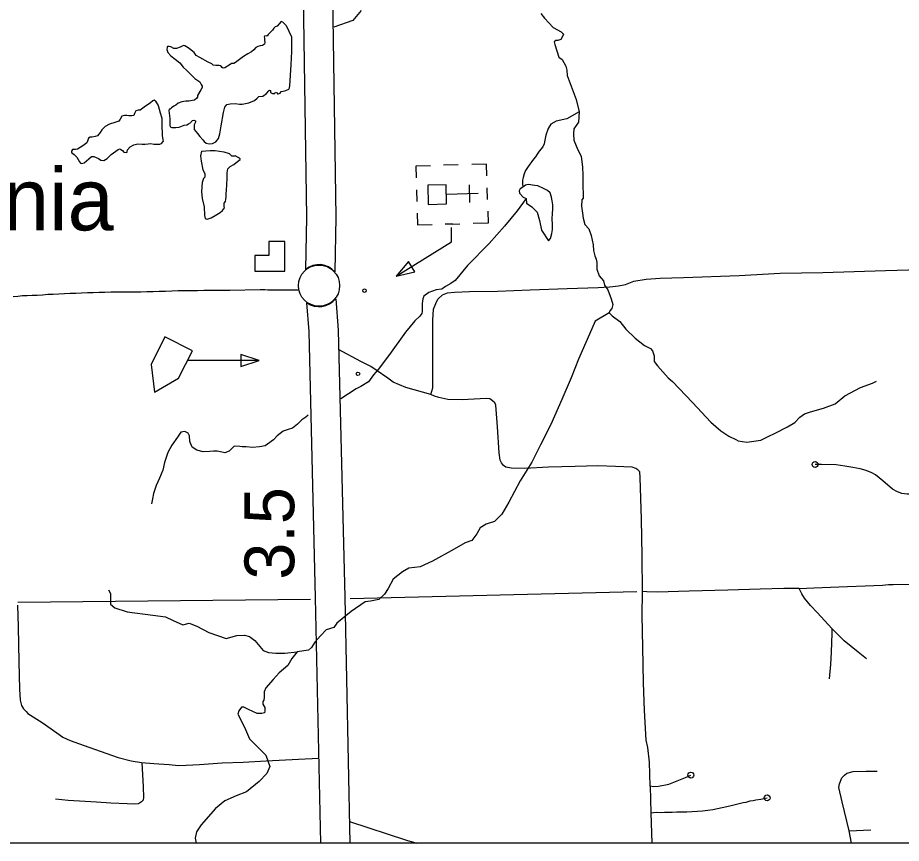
# Model space of a CAD drawing. Extents: x 1367863 to 1368197, y 380048 to 380261.
# Drawn here: x 1368043.62 to 1368072.73, y 380096.87 to 380124.07 of the extents above; entities that cross this region are included whole.
import ezdxf

# ---------------------------------------------------------------- set-up
doc = ezdxf.new("R2010")
doc.units = 0
for name, color, linetype in [('Level 10', 7, 'Continuous'), ('Level 24', 7, 'Continuous'), ('Level 31', 7, 'Continuous'), ('Level 35', 7, 'Continuous'), ('Level 48', 7, 'Continuous'), ('Level 5', 7, 'Continuous'), ('Level 57', 7, 'Continuous'), ('Level 58', 7, 'Continuous'), ('R_No Plot', 7, 'Continuous')]:
    doc.layers.add(name, color=color, linetype=linetype)

msp = doc.modelspace()

# ---------------------------------------------------------------- linework, layer by layer
at = {"layer": 'Level 10'}
for p, q in [((1368053.105, 380115.771), (1368053.107, 380115.776)), ((1368053.136, 380114.674), (1368053.137, 380114.676)), ((1368053.137, 380114.676), (1368053.136, 380114.674))]:
    msp.add_line(p, q, dxfattribs=at)
for points in [[(1368053.167, 380134.193), (1368052.97, 380133.946), (1368052.872, 380133.646), (1368052.827, 380133.421), (1368053.018, 380125.515), (1368053.136, 380117.497), (1368053.105, 380115.771)], [(1368054.074, 380115.691), (1368054.107, 380117.495), (1368053.989, 380125.533), (1368053.8, 380133.337), (1368053.812, 380133.399), (1368053.838, 380133.478), (1368053.927, 380133.59)], [(1368054.099, 380114.81), (1368054.177, 380113.773), (1368054.394, 380104.98), (1368054.565, 380096.865)], [(1368053.136, 380114.674), (1368053.208, 380113.724), (1368053.424, 380104.958), (1368053.595, 380096.865)]]:
    msp.add_lwpolyline(points, dxfattribs=at)
for centre, radius, start, end in [((1368053.546, 380115.239), 0.694, 40.6303, 129.2992), ((1368053.546, 380115.254), 0.708, 234.6739, 321.3402)]:
    msp.add_arc(centre, radius, start, end, dxfattribs=at)
at = {"layer": 'Level 24'}
msp.add_circle((1368053.548, 380115.239), 0.679, dxfattribs=at)
at = {"layer": 'Level 31'}
for points in [[(1368057.236, 380111.648), (1368057.296, 380111.876), (1368057.301, 380112.676), (1368057.301, 380114.098), (1368057.323, 380114.463), (1368057.398, 380114.651), (1368057.457, 380114.793), (1368057.618, 380114.933), (1368057.784, 380114.997), (1368058.01, 380115.024), (1368058.509, 380115.046), (1368059.432, 380115.062), (1368060.505, 380115.099), (1368061.717, 380115.142), (1368062.747, 380115.174), (1368063.123, 380115.196), (1368063.418, 380115.228), (1368063.643, 380115.282), (1368063.917, 380115.384), (1368064.319, 380115.448), (1368064.781, 380115.48), (1368065.555, 380115.507), (1368067.385, 380115.572), (1368068.737, 380115.647), (1368070.148, 380115.674), (1368072.214, 380115.733), (1368073.356, 380115.77)], [(1368052.854, 380115.087), (1368052.744, 380115.087), (1368052.599, 380115.087), (1368052.458, 380115.088), (1368052.322, 380115.09), (1368052.194, 380115.092), (1368052.072, 380115.093), (1368051.961, 380115.092), (1368051.86, 380115.092), (1368051.766, 380115.096), (1368051.683, 380115.097), (1368051.608, 380115.098), (1368050.606, 380115.081), (1368050.398, 380115.081), (1368050.186, 380115.081), (1368049.972, 380115.079), (1368049.756, 380115.078), (1368049.542, 380115.073), (1368049.328, 380115.068), (1368049.118, 380115.067), (1368048.909, 380115.063), (1368048.701, 380115.057), (1368048.494, 380115.049), (1368048.286, 380115.045), (1368048.083, 380115.036), (1368047.877, 380115.034), (1368047.674, 380115.029), (1368047.474, 380115.025), (1368047.275, 380115.024), (1368047.078, 380115.024), (1368046.883, 380115.023), (1368046.688, 380115.021), (1368046.495, 380115.016), (1368046.301, 380115.012), (1368046.109, 380115.007), (1368045.917, 380114.999), (1368045.727, 380114.991), (1368045.536, 380114.984), (1368045.346, 380114.975), (1368045.157, 380114.968), (1368044.978, 380114.953), (1368044.793, 380114.95), (1368044.608, 380114.946), (1368044.438, 380114.926), (1368044.266, 380114.918), (1368044.1, 380114.911), (1368043.937, 380114.905), (1368043.778, 380114.898), (1368043.624, 380114.886), (1368043.474, 380114.871)], [(1368057.236, 380111.648), (1368056.404, 380111.884), (1368055.991, 380112.056), (1368055.809, 380112.19), (1368055.428, 380112.459), (1368055.251, 380112.579), (1368054.924, 380112.74), (1368054.192, 380113.14)], [(1368064.203, 380105.156), (1368064.193, 380106.342), (1368064.166, 380107.55), (1368064.128, 380108.914), (1368064.118, 380109.107), (1368064.053, 380109.166), (1368063.983, 380109.214), (1368063.865, 380109.257), (1368063.318, 380109.279), (1368062.737, 380109.305), (1368061.986, 380109.284), (1368061.112, 380109.257), (1368060.323, 380109.214), (1368059.878, 380109.23), (1368059.701, 380109.262), (1368059.626, 380109.311), (1368059.561, 380109.397), (1368059.513, 380109.493), (1368059.486, 380109.735), (1368059.427, 380110.591), (1368059.373, 380111.299), (1368059.336, 380111.374), (1368059.261, 380111.444), (1368059.17, 380111.514), (1368059.052, 380111.525), (1368058.263, 380111.476), (1368057.789, 380111.487), (1368057.499, 380111.552), (1368057.354, 380111.6), (1368057.236, 380111.648)], [(1368074.44, 380108.399), (1368073.265, 380108.367), (1368072.922, 380108.367), (1368072.745, 380108.394), (1368072.6, 380108.442), (1368072.434, 380108.533), (1368072.117, 380108.807), (1368071.876, 380109.011), (1368071.758, 380109.07), (1368071.575, 380109.15), (1368071.371, 380109.199), (1368071.135, 380109.252), (1368070.867, 380109.295), (1368070.58, 380109.333), (1368070.103, 380109.349), (1368069.888, 380109.349)], [(1368069.368, 380105.261), (1368069.85, 380105.288), (1368070.671, 380105.315), (1368071.819, 380105.358), (1368072.109, 380105.369), (1368072.211, 380105.385), (1368072.308, 380105.396), (1368072.458, 380105.396), (1368073.252, 380105.406), (1368073.536, 380105.41)], [(1368064.459, 380098.753), (1368064.429, 380099.538), (1368064.375, 380100.021), (1368064.327, 380100.268), (1368064.273, 380101.236), (1368064.236, 380102.148), (1368064.219, 380103.324), (1368064.187, 380104.367), (1368064.203, 380105.156)], [(1368069.368, 380105.261), (1368068.863, 380105.261), (1368068.085, 380105.24), (1368067.012, 380105.202), (1368065.746, 380105.17), (1368064.7, 380105.143), (1368064.351, 380105.149), (1368064.203, 380105.159)], [(1368070.446, 380103.946), (1368069.963, 380104.462), (1368069.738, 380104.703), (1368069.539, 380104.939), (1368069.448, 380105.084), (1368069.368, 380105.261)], [(1368043.611, 380104.714), (1368043.638, 380103.995), (1368043.654, 380102.85), (1368043.681, 380101.948), (1368043.697, 380101.587), (1368043.741, 380101.408), (1368043.816, 380101.295), (1368043.897, 380101.208), (1368043.957, 380101.144), (1368044.432, 380100.843), (1368044.912, 380100.508), (1368045.112, 380100.368), (1368045.35, 380100.249), (1368045.96, 380100.033), (1368046.928, 380099.694), (1368047.36, 380099.581), (1368047.7, 380099.532), (1368048.11, 380099.494)], [(1368070.446, 380103.946), (1368070.441, 380103.785), (1368070.414, 380103.158), (1368070.398, 380102.76), (1368070.355, 380102.288)], [(1368071.579, 380102.949), (1368071.304, 380103.163), (1368070.843, 380103.533), (1368070.446, 380103.946)], [(1368048.11, 380099.494), (1368048.612, 380099.462), (1368048.915, 380099.429), (1368049.174, 380099.435), (1368049.606, 380099.467), (1368050.358, 380099.521), (1368051.044, 380099.537), (1368051.811, 380099.581), (1368052.869, 380099.64), (1368053.536, 380099.669)], [(1368047.709, 380099.531), (1368047.754, 380098.729), (1368047.77, 380098.378), (1368047.754, 380098.292), (1368047.7, 380098.227), (1368047.602, 380098.162), (1368047.484, 380098.151), (1368047.23, 380098.167), (1368046.69, 380098.189), (1368046.215, 380098.216), (1368045.286, 380098.275), (1368044.871, 380098.324)], [(1368064.459, 380098.754), (1368064.574, 380098.737), (1368064.732, 380098.746), (1368065.068, 380098.816), (1368065.185, 380098.86), (1368065.616, 380099.039), (1368065.797, 380099.114)], [(1368071.088, 380096.865), (1368071.009, 380097.282), (1368070.781, 380098.231), (1368070.673, 380098.704), (1368070.691, 380098.824), (1368070.769, 380099.023), (1368070.853, 380099.113), (1368070.937, 380099.179), (1368071.147, 380099.233), (1368071.574, 380099.245), (1368071.938, 380099.245)], [(1368064.459, 380098.754), (1368064.459, 380098.753), (1368064.475, 380097.866)], [(1368064.475, 380097.866), (1368064.652, 380097.887), (1368064.818, 380097.886), (1368064.923, 380097.889), (1368065.042, 380097.892), (1368065.18, 380097.896), (1368065.333, 380097.9), (1368065.497, 380097.903), (1368065.667, 380097.907), (1368065.84, 380097.914), (1368066.013, 380097.924), (1368066.184, 380097.937), (1368066.353, 380097.956), (1368066.517, 380097.983), (1368066.676, 380098.016), (1368066.83, 380098.049), (1368066.979, 380098.082), (1368067.123, 380098.115), (1368067.258, 380098.147), (1368067.392, 380098.178), (1368067.521, 380098.209), (1368067.623, 380098.222), (1368067.753, 380098.261), (1368067.848, 380098.281), (1368067.937, 380098.299), (1368068.099, 380098.323), (1368068.308, 380098.362)], [(1368064.475, 380097.866), (1368064.509, 380096.865)], [(1368054.55, 380097.583), (1368056.432, 380096.972), (1368056.774, 380096.865)], [(1368071.009, 380097.282), (1368071.728, 380097.31)]]:
    msp.add_lwpolyline(points, dxfattribs=at)
for centre in [(1368069.888, 380109.349), (1368065.797, 380099.114), (1368068.308, 380098.362)]:
    msp.add_circle(centre, 0.097, dxfattribs=at)
at = {"layer": 'Level 35'}
for points in [[(1368054.939, 380124.303), (1368054.664, 380123.974), (1368054.033, 380123.754)], [(1368060.85, 380124.21), (1368060.972, 380124.05), (1368061.26, 380123.742), (1368061.529, 380123.601), (1368061.606, 380123.524), (1368061.555, 380123.422), (1368061.517, 380123.352), (1368061.414, 380123.32), (1368061.344, 380123.313), (1368061.292, 380123.269), (1368061.312, 380123.179), (1368061.446, 380122.762), (1368061.555, 380122.685), (1368061.683, 380122.474), (1368061.715, 380122.339), (1368061.722, 380122.166), (1368062.023, 380121.367), (1368062.119, 380120.963), (1368062.093, 380120.627), (1368061.94, 380120.409), (1368061.927, 380120.236), (1368061.946, 380120.031), (1368062.068, 380119.71), (1368062.183, 380119.505), (1368062.228, 380119.146), (1368062.241, 380118.883), (1368062.241, 380118.652), (1368062.247, 380118.12), (1368062.202, 380118.069), (1368062.196, 380117.857), (1368062.222, 380117.627), (1368062.247, 380117.46), (1368062.305, 380117.255), (1368062.433, 380117.107), (1368062.51, 380116.896), (1368062.581, 380116.582), (1368062.593, 380116.396), (1368062.632, 380116.223), (1368062.677, 380116.114), (1368062.702, 380116.005), (1368062.702, 380115.902), (1368062.702, 380115.787), (1368062.779, 380115.562), (1368062.914, 380115.395), (1368062.952, 380115.254), (1368063.061, 380115.101), (1368063.17, 380114.806), (1368063.221, 380114.613), (1368063.189, 380114.491), (1368063.125, 380114.408), (1368063.106, 380114.338), (1368063.209, 380114.248), (1368063.452, 380114.062), (1368063.651, 380113.805), (1368063.958, 380113.504), (1368064.266, 380113.267), (1368064.465, 380113.171), (1368064.529, 380113.087)], [(1368052.351, 380123.924), (1368052.295, 380123.938), (1368052.229, 380123.867), (1368052.168, 380123.792), (1368052.107, 380123.764), (1368052.055, 380123.726), (1368052.013, 380123.66), (1368051.947, 380123.589), (1368051.871, 380123.509), (1368051.838, 380123.462), (1368051.81, 380123.467), (1368051.754, 380123.462), (1368051.744, 380123.434), (1368051.749, 380123.392), (1368051.754, 380123.316), (1368051.763, 380123.26), (1368051.749, 380123.199), (1368051.683, 380123.147), (1368051.608, 380123.142), (1368051.532, 380123.119), (1368051.466, 380123.081), (1368051.401, 380123.01), (1368051.325, 380122.944), (1368051.198, 380122.874), (1368051.062, 380122.789), (1368050.798, 380122.591), (1368050.737, 380122.553), (1368050.666, 380122.553), (1368050.591, 380122.506), (1368050.44, 380122.412), (1368050.393, 380122.407), (1368050.36, 380122.422), (1368050.313, 380122.478), (1368050.261, 380122.497), (1368050.148, 380122.497), (1368050.059, 380122.506), (1368050.016, 380122.544), (1368049.899, 380122.605), (1368049.626, 380122.761), (1368049.499, 380122.827), (1368049.433, 380122.916), (1368049.39, 380122.958), (1368049.324, 380123.01), (1368049.235, 380123.071), (1368049.127, 380123.142), (1368049.08, 380123.151), (1368048.976, 380123.1), (1368048.854, 380123.057), (1368048.764, 380123.057), (1368048.665, 380123.109), (1368048.609, 380123.123), (1368048.557, 380123.123), (1368048.543, 380123.086), (1368048.538, 380123.02), (1368048.571, 380122.916), (1368048.661, 380122.812), (1368048.811, 380122.699), (1368048.957, 380122.577), (1368049.075, 380122.44), (1368049.193, 380122.323), (1368049.452, 380122.064), (1368049.621, 380121.951), (1368049.668, 380121.861), (1368049.696, 380121.809), (1368049.696, 380121.767), (1368049.659, 380121.687), (1368049.541, 380121.508), (1368049.541, 380121.447), (1368049.522, 380121.418), (1368049.442, 380121.353), (1368049.254, 380121.321), (1368049.155, 380121.321), (1368049.028, 380121.297), (1368048.91, 380121.25), (1368048.83, 380121.184), (1368048.764, 380121.151), (1368048.689, 380121.095), (1368048.642, 380121.048), (1368048.609, 380121.048), (1368048.595, 380121.005), (1368048.632, 380120.742), (1368048.628, 380120.605), (1368048.628, 380120.53), (1368048.647, 380120.473), (1368048.703, 380120.445), (1368048.83, 380120.445), (1368048.938, 380120.459), (1368049.103, 380120.525), (1368049.188, 380120.539), (1368049.249, 380120.572), (1368049.32, 380120.619), (1368049.334, 380120.638), (1368049.376, 380120.68), (1368049.419, 380120.695), (1368049.475, 380120.671), (1368049.475, 380120.624), (1368049.456, 380120.586), (1368049.437, 380120.539), (1368049.437, 380120.502), (1368049.437, 380120.388), (1368049.546, 380120.247)], [(1368052.351, 380123.924), (1368052.464, 380123.811), (1368052.643, 380123.439), (1368052.643, 380122.954), (1368052.62, 380122.511), (1368052.573, 380121.823), (1368052.549, 380121.715)], [(1368049.546, 380120.247), (1368049.626, 380120.153), (1368049.715, 380120.04), (1368049.758, 380119.983), (1368049.828, 380119.932), (1368049.927, 380119.913), (1368050.035, 380119.927), (1368050.153, 380119.979), (1368050.238, 380120.082), (1368050.285, 380120.242), (1368050.322, 380120.502), (1368050.398, 380120.939), (1368050.44, 380121.118), (1368050.511, 380121.203), (1368050.619, 380121.227), (1368050.789, 380121.236), (1368050.925, 380121.217), (1368051.019, 380121.217), (1368051.231, 380121.264), (1368051.419, 380121.34), (1368051.509, 380121.415), (1368051.565, 380121.467), (1368051.697, 380121.486), (1368051.819, 380121.571), (1368051.89, 380121.655), (1368051.918, 380121.674), (1368051.947, 380121.665), (1368051.947, 380121.632), (1368051.947, 380121.604), (1368052.013, 380121.571), (1368052.088, 380121.575), (1368052.116, 380121.613), (1368052.173, 380121.594), (1368052.177, 380121.561), (1368052.201, 380121.556), (1368052.267, 380121.58), (1368052.295, 380121.636), (1368052.37, 380121.646), (1368052.455, 380121.669), (1368052.549, 380121.715)], [(1368048.158, 380121.322), (1368048.12, 380121.345), (1368048.069, 380121.331), (1368047.998, 380121.261), (1368047.791, 380121.115), (1368047.654, 380121.025), (1368047.593, 380121.02), (1368047.513, 380120.997), (1368047.466, 380120.907), (1368047.442, 380120.846), (1368047.386, 380120.832), (1368047.287, 380120.832), (1368047.217, 380120.841), (1368047.137, 380120.846), (1368047.056, 380120.818), (1368047, 380120.728), (1368046.948, 380120.653), (1368046.826, 380120.611), (1368046.647, 380120.564), (1368046.501, 380120.484), (1368046.397, 380120.375), (1368046.336, 380120.29), (1368046.251, 380120.177), (1368046.171, 380120.149), (1368046.073, 380120.13), (1368046.011, 380120.135), (1368045.955, 380120.097), (1368045.922, 380119.999), (1368045.903, 380119.942), (1368045.767, 380119.843), (1368045.588, 380119.735), (1368045.526, 380119.73), (1368045.475, 380119.73), (1368045.428, 380119.721), (1368045.395, 380119.669), (1368045.395, 380119.622), (1368045.479, 380119.556), (1368045.574, 380119.471), (1368045.658, 380119.32), (1368045.691, 380119.269), (1368045.724, 380119.264), (1368045.814, 380119.283), (1368045.814, 380119.287), (1368045.96, 380119.415), (1368046.054, 380119.49), (1368046.129, 380119.49), (1368046.28, 380119.433), (1368046.36, 380119.377), (1368046.459, 380119.363), (1368046.567, 380119.424), (1368046.703, 380119.565), (1368046.859, 380119.674), (1368046.929, 380119.73), (1368046.986, 380119.744), (1368047.014, 380119.73), (1368047.075, 380119.692), (1368047.113, 380119.636), (1368047.212, 380119.626), (1368047.231, 380119.664), (1368047.235, 380119.716), (1368047.325, 380119.815), (1368047.442, 380119.876), (1368047.579, 380119.914), (1368047.716, 380119.9), (1368047.819, 380119.895), (1368047.923, 380119.909), (1368048.007, 380119.918), (1368048.106, 380119.9), (1368048.172, 380119.904), (1368048.252, 380119.904), (1368048.299, 380119.904), (1368048.356, 380119.923), (1368048.417, 380119.984)], [(1368048.158, 380121.322), (1368048.252, 380121.176), (1368048.313, 380120.936), (1368048.365, 380120.761), (1368048.365, 380120.554), (1368048.384, 380120.173), (1368048.398, 380120.055), (1368048.417, 380119.984)], [(1368062.119, 380120.963), (1368061.706, 380120.73), (1368061.354, 380120.653), (1368061.189, 380120.554), (1368061.101, 380120.422), (1368061.024, 380120.202), (1368060.991, 380120.037), (1368060.969, 380119.916), (1368060.925, 380119.816), (1368060.804, 380119.673), (1368060.738, 380119.574), (1368060.683, 380119.486), (1368060.617, 380119.409), (1368060.562, 380119.332), (1368060.496, 380119.244), (1368060.419, 380119.134), (1368060.353, 380119.035), (1368060.309, 380118.925), (1368060.277, 380118.804), (1368060.255, 380118.716), (1368060.255, 380118.595), (1368060.266, 380118.485), (1368060.178, 380118.43), (1368060.145, 380118.364), (1368060.156, 380118.287), (1368060.277, 380118.155), (1368060.375, 380118.111), (1368060.386, 380117.957), (1368060.562, 380117.836), (1368060.738, 380117.66), (1368060.815, 380117.385), (1368060.881, 380117.066), (1368061.112, 380116.714), (1368061.178, 380116.791), (1368061.222, 380116.956), (1368061.244, 380117.088), (1368061.244, 380117.253), (1368061.233, 380117.44), (1368061.244, 380117.616), (1368061.255, 380117.759), (1368061.255, 380117.902), (1368061.233, 380118.034), (1368061.211, 380118.155), (1368061.167, 380118.298), (1368061.079, 380118.375), (1368060.947, 380118.441), (1368060.76, 380118.529), (1368060.661, 380118.54), (1368060.441, 380118.573), (1368060.353, 380118.551)], [(1368049.674, 380119.674), (1368049.646, 380119.513), (1368049.66, 380119.344), (1368049.721, 380119.057), (1368049.782, 380118.929), (1368049.787, 380118.816), (1368049.74, 380118.774), (1368049.702, 380118.642), (1368049.674, 380118.346), (1368049.693, 380118.11), (1368049.759, 380117.837), (1368049.773, 380117.55), (1368049.792, 380117.451), (1368049.857, 380117.427), (1368049.989, 380117.474), (1368050.126, 380117.55), (1368050.295, 380117.644), (1368050.366, 380117.719), (1368050.432, 380117.804), (1368050.422, 380117.851), (1368050.418, 380117.908), (1368050.422, 380117.955), (1368050.469, 380118.011), (1368050.479, 380118.077), (1368050.484, 380118.181), (1368050.484, 380118.265), (1368050.498, 380118.388), (1368050.512, 380118.562), (1368050.517, 380118.783), (1368050.517, 380118.958), (1368050.54, 380119.085), (1368050.62, 380119.16), (1368050.743, 380119.226), (1368050.865, 380119.325), (1368050.945, 380119.391), (1368050.945, 380119.419), (1368050.884, 380119.466), (1368050.79, 380119.518)], [(1368049.674, 380119.674), (1368049.961, 380119.692), (1368050.126, 380119.697), (1368050.408, 380119.645), (1368050.587, 380119.593), (1368050.663, 380119.518), (1368050.733, 380119.518), (1368050.79, 380119.518)], [(1368060.353, 380118.551), (1368060.266, 380118.485)], [(1368060.375, 380118.111), (1368060.079, 380117.704), (1368059.661, 380117.198), (1368059.155, 380116.626), (1368058.44, 380115.899), (1368058.033, 380115.404), (1368057.89, 380115.305), (1368057.714, 380115.206), (1368057.593, 380115.118), (1368057.406, 380115.096), (1368057.164, 380115.008), (1368056.999, 380114.887), (1368056.966, 380114.81), (1368056.944, 380114.656), (1368056.944, 380114.491), (1368056.944, 380114.392), (1368056.933, 380114.326), (1368056.867, 380114.238), (1368056.702, 380114.084), (1368056.394, 380113.71), (1368055.866, 380112.973), (1368055.492, 380112.478), (1368055.338, 380112.302), (1368055.173, 380112.07), (1368054.92, 380111.916), (1368054.766, 380111.839), (1368054.265, 380111.507)], [(1368063.106, 380114.338), (1368062.645, 380114.064), (1368062.462, 380113.637), (1368062.097, 380112.815), (1368061.853, 380112.205), (1368061.549, 380111.49), (1368061.183, 380110.667), (1368060.848, 380109.997), (1368060.559, 380109.418), (1368060.178, 380108.809), (1368059.797, 380108.108), (1368059.569, 380107.712), (1368059.325, 380107.468), (1368059.051, 380107.377), (1368058.853, 380107.255), (1368058.747, 380107.057), (1368058.579, 380106.844), (1368058.366, 380106.767), (1368058.001, 380106.554), (1368057.285, 380106.158), (1368056.874, 380105.975), (1368056.509, 380105.93), (1368056.295, 380105.808), (1368055.991, 380105.564), (1368055.823, 380105.259), (1368055.702, 380105.077), (1368055.519, 380104.894), (1368055.245, 380104.848), (1368055.062, 380104.818), (1368054.605, 380104.498), (1368054.133, 380104.117), (1368054.038, 380103.974), (1368053.782, 380103.903), (1368053.596, 380103.698), (1368053.41, 380103.493), (1368053.301, 380103.313), (1368053.198, 380103.23), (1368052.829, 380103.175), (1368052.65, 380102.96), (1368052.525, 380102.719), (1368052.229, 380102.477), (1368052.041, 380102.262), (1368051.799, 380101.985), (1368051.737, 380101.859), (1368051.737, 380101.68), (1368051.728, 380101.582), (1368051.692, 380101.537), (1368051.692, 380101.448), (1368051.764, 380101.34), (1368051.764, 380101.233), (1368051.746, 380101.161), (1368051.665, 380101.143), (1368051.513, 380101.143), (1368051.227, 380101.278), (1368051.074, 380101.349), (1368050.994, 380101.349), (1368050.904, 380101.233), (1368050.877, 380101.116), (1368051.092, 380100.696), (1368051.256, 380100.313)], [(1368064.529, 380113.087), (1368064.586, 380112.925), (1368064.593, 380112.841), (1368064.593, 380112.739), (1368064.702, 380112.598), (1368065.054, 380112.2), (1368065.189, 380112.085), (1368065.849, 380111.392), (1368066.451, 380110.745), (1368066.785, 380110.456), (1368067.047, 380110.277), (1368067.278, 380110.168), (1368067.36, 380110.121), (1368067.643, 380110.084), (1368068.099, 380110.148), (1368068.348, 380110.264), (1368068.573, 380110.379), (1368068.983, 380110.584), (1368069.22, 380110.725), (1368069.387, 380110.905), (1368069.54, 380111.02), (1368069.733, 380111.078), (1368070.169, 380111.206), (1368070.547, 380111.341), (1368070.874, 380111.604), (1368071.386, 380111.886), (1368071.777, 380112.027), (1368071.912, 380112.091)], [(1368053.195, 380110.973), (1368053.116, 380110.904), (1368052.984, 380110.816), (1368052.841, 380110.673), (1368052.676, 380110.541), (1368052.533, 380110.497), (1368052.368, 380110.442), (1368052.17, 380110.288), (1368052.049, 380110.156), (1368051.851, 380110.013), (1368051.774, 380109.958), (1368051.587, 380109.925), (1368051.356, 380109.903), (1368051.147, 380109.925), (1368051.015, 380109.925), (1368050.938, 380109.936), (1368050.751, 380109.947), (1368050.586, 380109.782), (1368050.443, 380109.727), (1368050.3, 380109.76), (1368050.19, 380109.782), (1368050.069, 380109.782), (1368049.948, 380109.771), (1368049.728, 380109.76), (1368049.519, 380109.815), (1368049.365, 380109.914), (1368049.288, 380110.101), (1368049.277, 380110.288), (1368049.233, 380110.376), (1368049.123, 380110.431), (1368048.991, 380110.409), (1368048.881, 380110.244), (1368048.694, 380109.98), (1368048.562, 380109.738), (1368048.452, 380109.408), (1368048.397, 380109.155), (1368048.287, 380108.891), (1368048.177, 380108.649), (1368048.089, 380108.395), (1368048.056, 380108.219), (1368048.023, 380108.054)], [(1368046.613, 380105.222), (1368046.679, 380105.091), (1368046.679, 380104.741), (1368046.822, 380104.625), (1368047.225, 380104.491), (1368048.075, 380104.383), (1368048.487, 380104.33), (1368048.738, 380104.204), (1368049.06, 380104.061), (1368049.266, 380104.124), (1368049.526, 380104.016), (1368049.92, 380103.811), (1368050.492, 380103.614), (1368050.842, 380103.712), (1368051.092, 380103.721), (1368051.253, 380103.676), (1368051.432, 380103.551), (1368051.71, 380103.22), (1368051.88, 380103.148), (1368052.122, 380103.13), (1368052.426, 380103.13), (1368052.829, 380103.175)], [(1368051.256, 380100.313), (1368051.512, 380100.054), (1368051.791, 380099.775), (1368051.931, 380099.391), (1368051.827, 380099.171), (1368051.575, 380098.903), (1368051.158, 380098.563), (1368050.818, 380098.434), (1368050.44, 380098.261), (1368050.132, 380098.017), (1368049.664, 380097.479), (1368049.51, 380097.241), (1368049.465, 380097.03), (1368049.504, 380096.865)]]:
    msp.add_lwpolyline(points, dxfattribs=at)
at = {"layer": 'Level 5'}
for points in [[(1368064.02, 380105.15), (1368054.569, 380104.923)], [(1368053.265, 380104.9), (1368043.629, 380104.8)]]:
    msp.add_lwpolyline(points, dxfattribs=at)
at = {"layer": 'Level 57'}
for p, q in [((1368058.136, 380119.216), (1368057.651, 380119.203)), ((1368058.488, 380118.559), (1368058.504, 380117.977)), ((1368056.755, 380118.4), (1368056.765, 380118.012)), ((1368058.787, 380118.276), (1368057.742, 380118.247)), ((1368059.093, 380118.076), (1368059.082, 380118.464)), ((1368057.951, 380117.27), (1368057.705, 380117.263)), ((1368057.951, 380117.27), (1368058.19, 380117.277))]:
    msp.add_line(p, q, dxfattribs=at)
for points in [[(1368057.218, 380119.191), (1368056.733, 380119.178), (1368056.744, 380118.79)], [(1368059.072, 380118.854), (1368059.061, 380119.242), (1368058.576, 380119.229)], [(1368056.776, 380117.626), (1368056.787, 380117.238), (1368057.272, 380117.251)], [(1368059.104, 380117.69), (1368059.115, 380117.302), (1368058.63, 380117.289)], [(1368056.09, 380115.551), (1368057.916, 380116.681), (1368057.916, 380117.16)], [(1368051.57, 380112.768), (1368049.223, 380112.768)]]:
    msp.add_lwpolyline(points, dxfattribs=at)
for points in [[(1368057.145, 380117.917), (1368057.751, 380117.934), (1368057.733, 380118.562), (1368057.128, 380118.545)], [(1368056.699, 380115.695), (1368056.491, 380116.032), (1368056.09, 380115.551)], [(1368049.374, 380113.096), (1368048.471, 380113.548), (1368048.019, 380112.645), (1368048.125, 380111.729), (1368048.922, 380112.193)], [(1368050.976, 380112.966), (1368050.976, 380112.57), (1368051.57, 380112.768)]]:
    msp.add_lwpolyline(points, close=True, dxfattribs=at)
for centre in [(1368055.047, 380115.073), (1368054.83, 380112.333)]:
    msp.add_circle(centre, 0.0582, dxfattribs=at)
at = {"layer": 'Level 58'}
msp.add_lwpolyline([(1368052.416, 380115.711), (1368052.416, 380116.696), (1368051.896, 380116.696), (1368051.896, 380116.23), (1368051.43, 380116.23), (1368051.43, 380115.711)], close=True, dxfattribs=at)
at = {"layer": 'R_No Plot'}
msp.add_lwpolyline([(1367959.444, 380177.46), (1368103.344, 380177.46), (1368103.344, 380096.865), (1367959.444, 380096.865)], close=True, dxfattribs=at)

# ---------------------------------------------------------------- texts
at = {"layer": 'Level 24'}
msp.add_text('Sylvania', height=2.0492, dxfattribs=at).set_placement((1368036.43, 380117.06))
at = {"layer": 'Level 48'}
msp.add_text('3.5', height=1.6394, rotation=90, dxfattribs=at).set_placement((1368052.731, 380105.552))

doc.saveas('drawing.dxf')
